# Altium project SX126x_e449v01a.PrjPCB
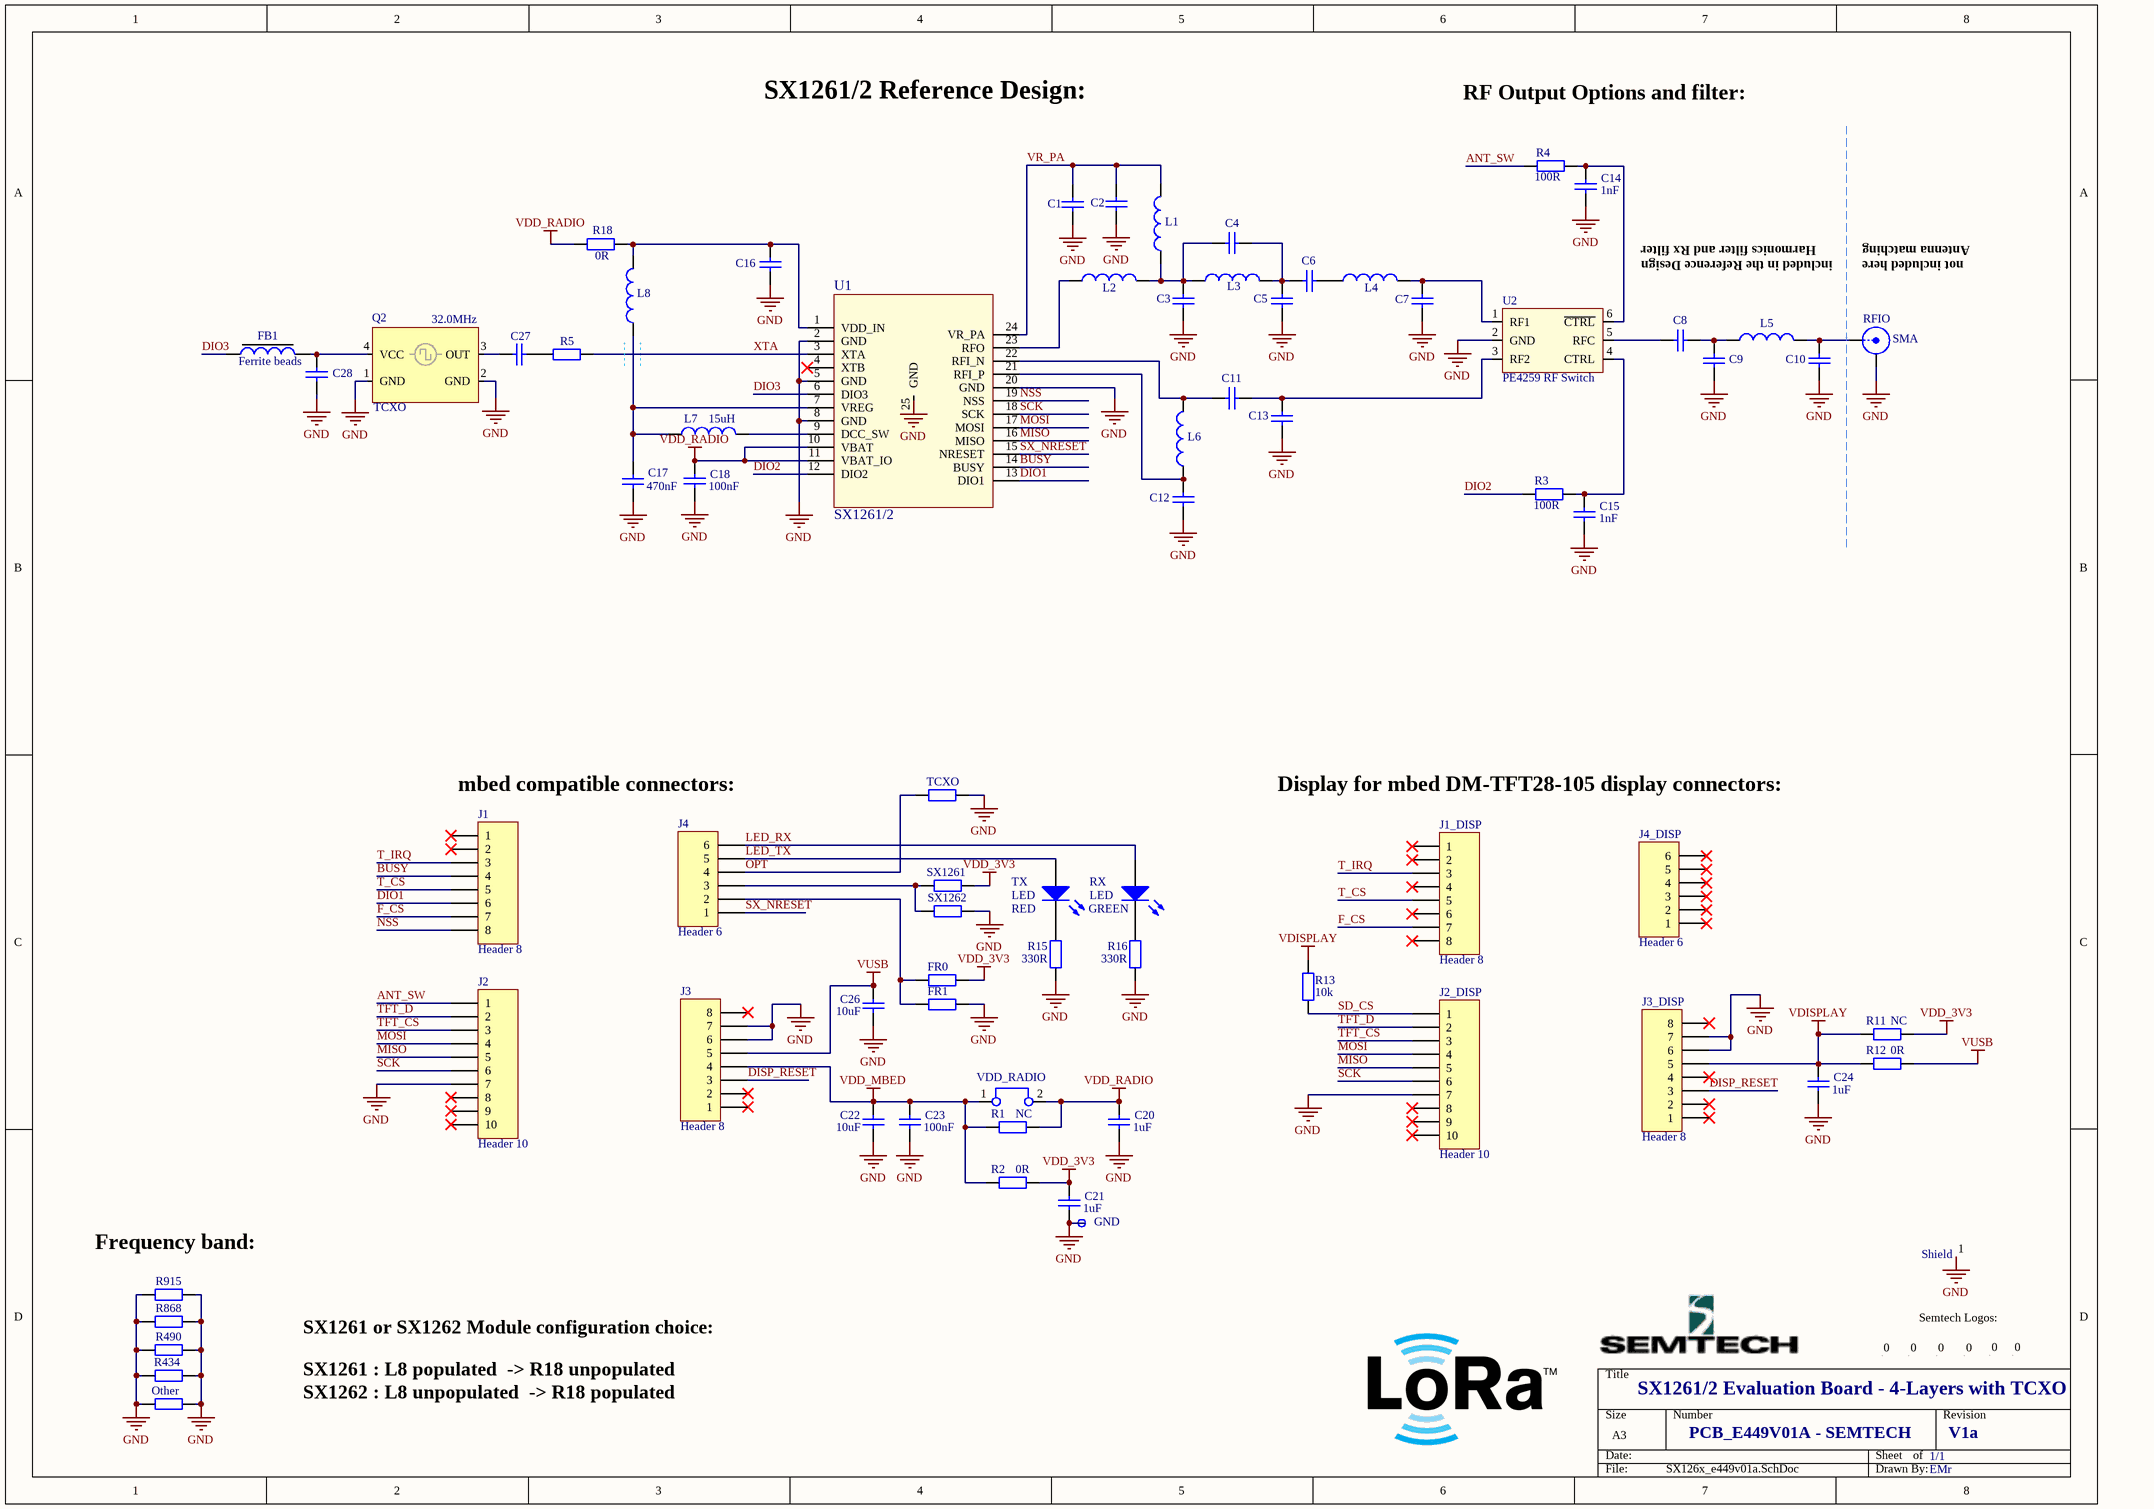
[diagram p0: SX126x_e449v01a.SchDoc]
1 sheet, 79 parts. Net scope: global (net labels, ports and power ports of the same name join across sheets).
Board file: SX126x_e449v01a.PcbDoc

## Sheet SX126x_e449v01a.SchDoc
size A3; DocumentNumber: 1; SheetNumber: 1; SheetTotal: 2

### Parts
C1  Cap  [rlc_402_smd]  (value not drawn)
C2  Cap  [rlc_402_smd]  (value not drawn)
C3  Cap  [rlc_402_smd]  (value not drawn)
C4  Cap  [rlc_402_smd]  (value not drawn)
C5  Cap  [rlc_402_smd]  (value not drawn)
C6  Cap  [rlc_402_smd]  (value not drawn)
C7  Cap  [rlc_402_smd]  (value not drawn)
C8  Cap  [rlc_402_smd]  (value not drawn)
C9  Cap  [rlc_402_smd]  (value not drawn)
C10  Cap  [rlc_402_smd]  (value not drawn)
C11  Cap  [rlc_402_smd]  (value not drawn)
C12  Cap  [rlc_402_smd]  (value not drawn)
C13  Cap  [rlc_402_smd]  (value not drawn)
C14  value 1nF  [rlc_402_smd]  (hidden comment: Cap)
C15  value 1nF  [rlc_402_smd]  (hidden comment: Cap)
C16  Cap  [rlc_402_smd]  (value not drawn)
C17  value 470nF  [rlc_402_smd]  (hidden comment: Cap)
C18  value 100nF  [rlc_402_smd]  (hidden comment: Cap)
C20  value 1uF  [rlc_603_smd]  (hidden comment: Cap)
C21  value 1uF  [rlc_603_smd]  (hidden comment: Cap)
C22  value 10uF  [rlc_805_smd]  (hidden comment: Cap)
C23  value 100nF  [rlc_402_smd]  (hidden comment: Cap)
C24  value 1uF  [rlc_402_smd]  (hidden comment: Cap)
C26  value 10uF  [rlc_805_smd]  (hidden comment: Cap)
C27  Cap  [rlc_402_smd]  (value not drawn)
C28  Cap  [rlc_402_smd]  (value not drawn)
FB1  Ferrite beads  [rlc_402_smd]
FR0  Resistor  [rlc_402_smd]  (value not drawn)
FR1  Resistor  [rlc_402_smd]  (value not drawn)
GND  Test Pin  [pin_0.9mm]  (value not drawn)
J1  Header 8  [HDR1X8]
J1_DISP  Header 8  [HDR1X8]
J2  Header 10  [HDR1X10]
J2_DISP  Header 10  [HDR1X10]
J3  Header 8  [HDR1X8]
J3_DISP  Header 8  [HDR1X8]
J4  Header 6  [HDR1X6]
J4_DISP  Header 6  [HDR1X6]
L1  Inductor  [rlc_402_smd]  (value not drawn)
L2  Inductor  [rlc_402_smd]  (value not drawn)
L3  Inductor  [rlc_402_smd]  (value not drawn)
L4  Inductor  [rlc_402_smd]  (value not drawn)
L5  Inductor  [rlc_402_smd]  (value not drawn)
L6  Inductor  [rlc_402_smd]  (value not drawn)
L7  value 15uH  [rlc_805_smd enlarged]  (hidden comment: Inductor)
L8  Inductor  [rlc_402_smd]  (value not drawn)
Logo_Bot  Logo symbol  [logo_semtech_horiz_size4]  (value not drawn)
Logo_ESD  Logo symbol  [Logo ESD]  (value not drawn)
Logo_LoRA1  Logo symbol  [Logo LoRa Size4]  (value not drawn)
Logo_LoRA2  Logo symbol  [Logo LoRa Size3]  (value not drawn)
Logo_Recycling1  Logo symbol  [Logo Recycling1]  (value not drawn)
Logo_Semtech_S  Logo symbol  [logo_semtech_horiz_size3]  (value not drawn)
Other  Resistor  [rlc_402_smd]  (value not drawn)
Q2  TCXO  value 32.0MHz  [TCXO 2.0x1.6mm]
R1  value NC  [rlc_603_smd]  (hidden comment: Resistor)
R2  value 0R  [rlc_603_smd]  (hidden comment: Resistor)
R3  value 100R  [rlc_402_smd]  (hidden comment: Resistor)
R4  value 100R  [rlc_402_smd]  (hidden comment: Resistor)
R5  Resistor  [rlc_402_smd]  (value not drawn)
R11  value NC  [rlc_402_smd]  (hidden comment: Resistor)
R12  value 0R  [rlc_402_smd]  (hidden comment: Resistor)
R13  value 10k  [rlc_402_smd]  (hidden comment: Resistor)
R15  value 330R  [rlc_402_smd]  (hidden comment: Resistor)
R16  value 330R  [rlc_402_smd]  (hidden comment: Resistor)
R18  value 0R  [rlc_402_smd]  (hidden comment: Resistor)
R434  Resistor  [rlc_402_smd]  (value not drawn)
R490  Resistor  [rlc_402_smd]  (value not drawn)
R868  Resistor  [rlc_402_smd]  (value not drawn)
R915  Resistor  [rlc_402_smd]  (value not drawn)
RFIO  SMA  [SMA_end_launch_1.0mm_9.52mm]
RX  LED  value GREEN  [LGM676 LED]
Shield  Logo symbol  [BMIS-209-F - Shield - Solder_Mask]  (value not drawn)
SX1261  Resistor  [rlc_402_smd]  (value not drawn)
SX1262  Resistor  [rlc_402_smd]  (value not drawn)
TCXO  Resistor  [rlc_402_smd]  (value not drawn)
TX  LED  value RED  [LGM676 LED]
U1  SX1261/2  [vqfn24_4x4mm]
U2  PE4259 RF Switch  [SC70-6]
VDD_RADIO  Jumper  [bridge_254mm]  (value not drawn)

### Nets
GND: C1.1 C2.1 C3.1 C5.1 C7.1 C9.1 C10.1 C12.1 C13.1 C14.2 C15.2 C16.1 C17.1 C18.1 C20.1 C21.1 C22.1 C23.1 C24.1 C26.1 C28.1 FR1.1 GND.1(pin) J2.7 J2_DISP.7 J3.6 J3.7 J3_DISP.6 J3_DISP.7 Other.1 Other.2 Q2.1(GND) Q2.2(GND) R15.1 R16.1 R434.1 R434.2 R490.1 R490.2 R868.1 R868.2 R915.1 R915.2 RFIO.2(GND) Shield.1 SX1262.1 TCXO.1 U1.2(GND) U1.5(GND) U1.8(GND) U1.20(GND) U1.25(GND) U2.2(GND)
VDD_3V3: C21.2 FR0.1 R2.1 R11.1 SX1261.1
VDD_MBED: C22.2 C23.2 J3.4 R1.2 R2.2 VDD_RADIO.1
VDD_RADIO: C18.2 C20.2 R1.1 R18.2 U1.10(VBAT) U1.11(VBAT_IO) VDD_RADIO.2
VDISPLAY: C24.2 J3_DISP.5 R11.2 R12.2 R13.1
VUSB: C26.2 J3.5 R12.1
ANT_SW: J2.1 R4.2
BUSY: J1.4 U1.14(BUSY)
DIO1: J1.6 U1.13(DIO1)
DIO2: R3.2 U1.12(DIO2)
DIO3: FB1.1 U1.6(DIO3)
DISP_RESET: J3.3 J3_DISP.3
F_CS: J1.7 J1_DISP.7
LED_RX: J4.6 RX.1(A)
LED_TX: J4.5 TX.1(A)
MISO: J2.5 J2_DISP.5 U1.16(MISO)
MOSI: J2.4 J2_DISP.4 U1.17(MOSI)
NSS: J1.8 U1.19(NSS)
OPT: J4.4 TCXO.2
SCK: J2.6 J2_DISP.6 U1.18(SCK)
SD_CS: J2_DISP.1 R13.2
SX_NRESET: J4.1 U1.15(NRESET)
T_CS: J1.5 J1_DISP.5
T_IRQ: J1.3 J1_DISP.3
TFT_CS: J2.3 J2_DISP.3
TFT_D: J2.2 J2_DISP.2
VR_PA: C1.2 C2.2 L1.2 U1.24(VR_PA)
XTA: R5.1 U1.3(XTA)
NetC3_2: C3.2 C4.2 L1.1 L2.2 L3.1
NetC4_1: C4.1 C5.2 C6.2 L3.2
NetC6_1: C6.1 L4.1
NetC7_2: C7.2 L4.2 U2.1(RF1)
NetC8_1: C8.1 C9.2 L5.1
NetC8_2: C8.2 U2.5(RFC)
NetC10_2: C10.2 L5.2 RFIO.1(Signal)
NetC11_1: C11.1 C13.2 U2.3(RF2)
NetC11_2: C11.2 L6.2 U1.22(RFI_N)
NetC12_2: C12.2 L6.1 U1.21(RFI_P)
NetC14_1: C14.1 R4.1 U2.6(~{CTRL})
NetC15_1: C15.1 R3.1 U2.4(CTRL)
NetC16_2: C16.2 L8.1 R18.1 U1.1(VDD_IN)
NetC17_2: C17.2 L7.1 L8.2 U1.7(VREG)
NetC27_1: C27.1 Q2.3(OUT)
NetC27_2: C27.2 R5.2
NetC28_2: C28.2 FB1.2 Q2.4(VCC)
NetFR0_2: FR0.2 FR1.2 J4.2
NetJ4_3: J4.3 SX1261.2 SX1262.2
NetL2_1: L2.1 U1.23(RFO)
NetL7_2: L7.2 U1.9(DCC_SW)
NetR15_2: R15.2 TX.2(K)
NetR16_2: R16.2 RX.2(K)

Not connected (* = marked no-connect by the designer): J1 1* 2*; J1_DISP 1* 2* 4* 6* 8*; J2 8* 9* 10*; J2_DISP 8* 9* 10*; J3 1* 2* 8*; J3_DISP 1* 2* 4* 8*; J4_DISP 1* 2* 3* 4* 5* 6*; Logo_Bot 0; Logo_ESD 0; Logo_LoRA1 0; Logo_LoRA2 0; Logo_Recycling1 0; Logo_Semtech_S 0; U1 4(XTB)*

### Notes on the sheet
- SX1261/2 Reference Design:
- RF Output Options and filter:
- Harmonics filter and Rx filter
- Antenna matching
- included in the Reference Design
- not included here
- mbed compatible connectors:
- Display for mbed DM-TFT28-105 display connectors:
- (near R915) Frequency band:
- Semtech Logos:
- SX1261 : L8 populated  -> R18 unpopulated
- SX1261 or SX1262 Module configuration choice:
- SX1261/2 Evaluation Board - 4-Layers with TCXO
- SX1262 : L8 unpopulated  -> R18 populated
- PCB_E449V01A - SEMTECH
- 1/1
- V1a
- EMr

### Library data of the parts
C1-C13 = Cap: Capacitor SMD; Value: NC
C14 C15 C17 C18 C20-C24 C26 = Cap: Capacitor SMD
C16 = Cap: Capacitor SMD; Value: 1uF
C27 = Cap: Capacitor SMD; Value: 15pF
C28 = Cap: Capacitor SMD; Value: 100nF
FB1 = Ferrite beads: Value: NC
FR0 = Resistor: Resistor SMD - IEC symbol version; Value: 1k
FR1 Other R434 R490 R868 R915 SX1261 TCXO = Resistor: Resistor SMD - IEC symbol version; Value: NC
GND = test_pin
J1 J1_DISP J3 J3_DISP = Header 8: Header, 8-Pin
J2 J2_DISP = Header 10: Header, 10-Pin
J4 J4_DISP = Header 6: Header, 6-Pin
L1-L6 = Inductor: Inductor SMD; Code_IEC: 1005; Value: 0R
L7 = Inductor: Inductor SMD; Code_IEC: 1005
L8 = Inductor: Inductor SMD; Value: 47nH; Code_IEC: 1005
Logo_Bot Logo_ESD Logo_LoRA1 Logo_LoRA2 Logo_Recycling1 Logo_Semtech_S = Logo: Schematic symbol for Logo
R1-R5 R11-R13 R15 R16 R18 = Resistor: Resistor SMD - IEC symbol version
RFIO = SMA: SMA Straight Connector
Shield = Shield: Shield - EMI Gasket - Standard Surface Mount Shields
SX1262 = Resistor: Resistor SMD - IEC symbol version; Value: 10k
U1 = SX126x: SX1261/2 - Ultra low power RF transceiver
U2 = PE4259 RF Switch: PE4259 Peregrine RF Switch
VDD_RADIO = Jumper: Jumper Wire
